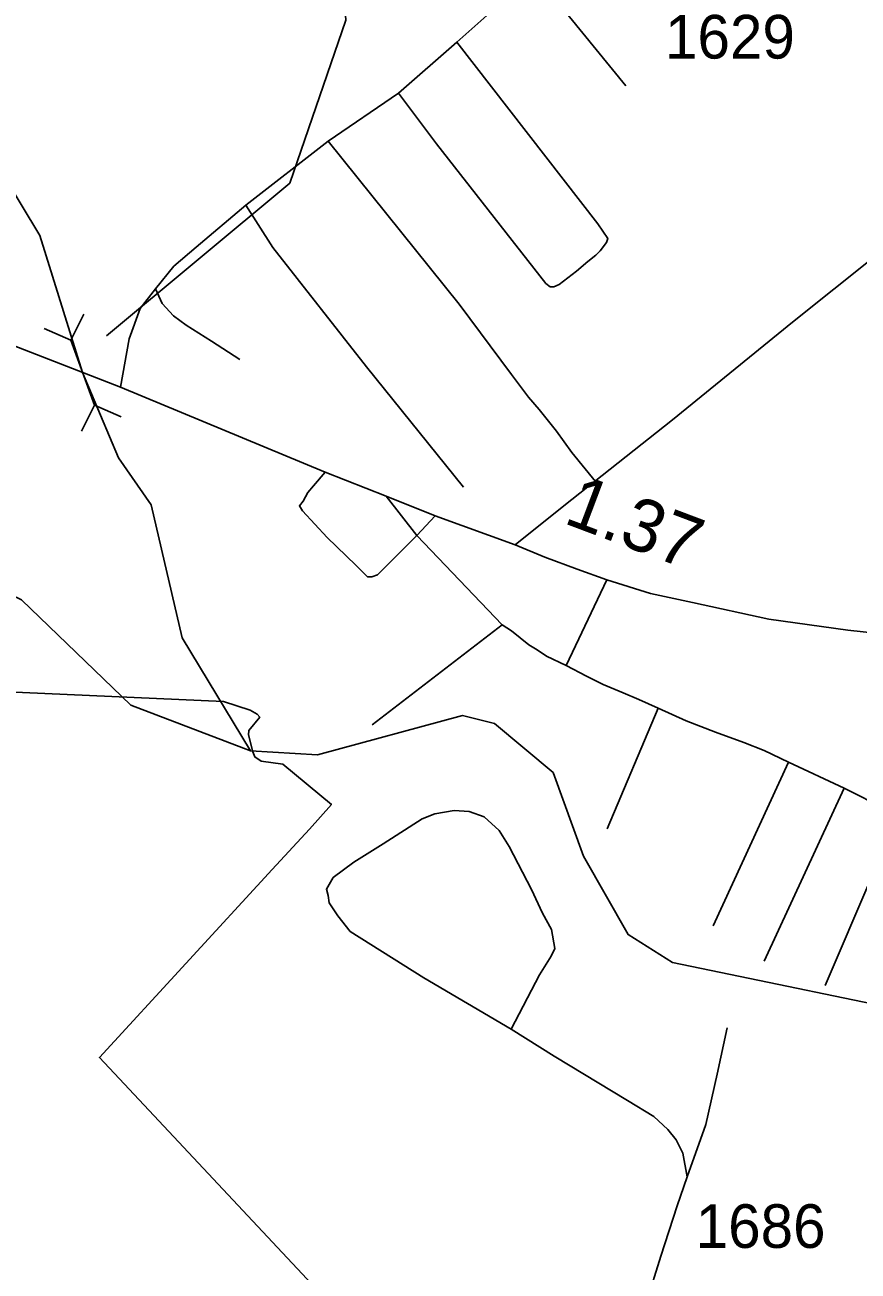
# Model space of a CAD drawing. Extents: x 2290615 to 2522933, y 819489 to 1012715.
# Drawn here: x 2393947 to 2396333, y 979017 to 982586 of the extents above; entities that cross this region are included whole.
import ezdxf

# ---------------------------------------------------------------- set-up
doc = ezdxf.new("R2010")
doc.units = 0
for name, color, linetype in [('Exist Boundary Political City Limit New', 7, 'Continuous'), ('Exist Boundary Political City Limit Old', 7, 'Continuous'), ('Exist Hydrographic Creek Single Shore', 7, 'Continuous'), ('Exist Road Non-System Type 51', 7, 'Continuous'), ('Exist Road Primary US Attributed', 7, 'Continuous'), ('Exist Road Primary US Mileage Hundredths English Label', 7, 'Continuous'), ('Exist Road Primary US Structure Culvert CELL', 7, 'Continuous'), ('Exist Road Primary US Structure Culvert Number Label', 7, 'Continuous'), ('Exist Road Secondary Type 51 Number Label', 7, 'Continuous'), ('Map Preparation Boundary City Limit Buffer Line', 7, 'Continuous')]:
    doc.layers.add(name, color=color, linetype=linetype)

msp = doc.modelspace()

# ---------------------------------------------------------------- linework, layer by layer
at = {"layer": 'Exist Boundary Political City Limit New'}
for points in [[(2393618.8, 980687.8), (2394515, 980647.9), (2394591.5, 980623), (2394611.9, 980611.5), (2394619.1, 980603.4), (2394588.3, 980565), (2394587.3, 980552.5), (2394598.9, 980503.4), (2394605.1, 980489.2), (2394623.3, 980476.9), (2394685.7, 980468.7), (2394824.5, 980353.1), (2394761.3, 980282)], [(2394761.3, 980282), (2394654.9, 980166.6), (2394160.2, 979627.9), (2395391.9, 978313.4)]]:
    msp.add_lwpolyline(points, dxfattribs=at)
at = {"layer": 'Exist Boundary Political City Limit Old'}
for points in [[(2393618.8, 980687.8), (2394515, 980647.9), (2394591.5, 980623), (2394611.9, 980611.5), (2394619.1, 980603.4), (2394588.3, 980565), (2394587.3, 980552.5), (2394598.9, 980503.4), (2394605.1, 980489.2), (2394623.3, 980476.9), (2394685.7, 980468.7), (2394824.5, 980353.1), (2394761.3, 980282)], [(2394761.3, 980282), (2394654.9, 980166.6), (2394160.2, 979627.9), (2395391.9, 978313.4)]]:
    msp.add_lwpolyline(points, dxfattribs=at)
at = {"layer": 'Exist Hydrographic Creek Single Shore'}
for points in [[(2393879.5, 982165.1), (2393989.6, 981982.5), (2394111.7, 981590.2), (2394214.7, 981346.3), (2394308.5, 981211), (2394396.7, 980830.6), (2394592.7, 980507)], [(2394592.7, 980507), (2394249.6, 980637.4), (2393936.5, 980939.6), (2393785.6, 981012.2), (2393361.6, 981007.9), (2393260.7, 981039.9), (2392687.6, 981492.4), (2392479.6, 981480.6), (2392349.6, 981235.5), (2392242.6, 981142.4), (2392002.7, 981024.2), (2391774.7, 980621)], [(2397518.6, 979136.9), (2397397.3, 979259.2), (2397358.2, 979428.8), (2397320.4, 979504.4), (2397230.5, 979527.9), (2397012.7, 979572.4), (2396904.7, 979581.1), (2396594.6, 979735.8), (2395800.7, 979900), (2395674.5, 979980.2), (2395546.6, 980204.8), (2395459.7, 980444.2), (2395291.5, 980585), (2395199.6, 980607.5), (2394784.6, 980495.2), (2394592.7, 980507)]]:
    msp.add_lwpolyline(points, dxfattribs=at)
at = {"layer": 'Exist Road Non-System Type 51'}
for p, q in [((2395183.3, 982536.4), (2395405.1, 982733.7)), ((2395183.3, 982536.4), (2395405.1, 982733.7)), ((2395405.1, 982733.7), (2395667.4, 982411.3)), ((2395405.1, 982733.7), (2395667.4, 982411.3)), ((2395016.1, 982390.2), (2395183.3, 982536.4)), ((2395016.1, 982390.2), (2395183.3, 982536.4)), ((2394815.4, 982252.8), (2395016.1, 982390.2)), ((2394815.4, 982252.8), (2395016.1, 982390.2)), ((2394579.5, 982069.5), (2394815.4, 982252.8)), ((2394579.5, 982069.5), (2394815.4, 982252.8)), ((2395068.9, 981123.4), (2394980.9, 981236.2)), ((2395068.9, 981123.4), (2394980.9, 981236.2)), ((2395068.9, 981123.4), (2395121.7, 981179.8)), ((2395068.9, 981123.4), (2395313.6, 980868)), ((2395068.9, 981123.4), (2395313.6, 980868)), ((2395496.5, 980750.7), (2395612.9, 980996.6)), ((2395496.5, 980750.7), (2395612.9, 980996.6)), ((2394941.1, 980580.9), (2395313.6, 980868)), ((2394941.1, 980580.9), (2395313.6, 980868)), ((2395614.2, 980282.9), (2395760.1, 980628.5)), ((2395614.2, 980282.9), (2395760.1, 980628.5)), ((2395917.9, 980005.7), (2396133.8, 980474.3)), ((2395917.9, 980005.7), (2396133.8, 980474.3)), ((2396133.8, 980474.3), (2396293.1, 980399.8)), ((2396133.8, 980474.3), (2396293.1, 980399.8)), ((2396063.8, 979904.4), (2396293.1, 980399.8)), ((2396063.8, 979904.4), (2396293.1, 980399.8)), ((2396293.1, 980399.8), (2396448, 980320.9)), ((2396293.1, 980399.8), (2396448, 980320.9)), ((2396238.1, 979834.4), (2396372.1, 980146.5)), ((2396238.1, 979834.4), (2396372.1, 980146.5))]:
    msp.add_line(p, q, dxfattribs=at)
for points in [[(2395183.3, 982536.4), (2395587.3, 982015.8), (2395616.4, 981974.4), (2395612, 981962.9), (2395594, 981938.9), (2395581.3, 981926.3), (2395558.8, 981908.1), (2395526.6, 981881), (2395476.4, 981842.3), (2395461.5, 981836.1), (2395450.9, 981836.1), (2395438.6, 981844.9), (2395125.2, 982245.7), (2395016.1, 982390.2)], [(2395183.3, 982536.4), (2395587.3, 982015.8), (2395616.4, 981974.4), (2395612, 981962.9), (2395594, 981938.9), (2395581.3, 981926.3), (2395558.8, 981908.1), (2395526.6, 981881), (2395476.4, 981842.3), (2395461.5, 981836.1), (2395450.9, 981836.1), (2395438.6, 981844.9), (2395125.2, 982245.7), (2395016.1, 982390.2)], [(2395350.6, 981097), (2395489.6, 981208), (2395801.2, 981454.7), (2396144.5, 981734.8), (2396500.1, 982018.4), (2396739.5, 982205.2), (2396852.2, 982291.5)], [(2395580.8, 981278.1), (2395513.3, 981361.6), (2395468.7, 981422.2), (2395419.6, 981484), (2395388.7, 981519.5), (2395340, 981585), (2395190.4, 981785.9), (2394815.4, 982252.8)], [(2395580.8, 981278.1), (2395513.3, 981361.6), (2395468.7, 981422.2), (2395419.6, 981484), (2395388.7, 981519.5), (2395340, 981585), (2395190.4, 981785.9), (2394815.4, 982252.8)], [(2394320.7, 981829.9), (2394373.5, 981895.1), (2394436.9, 981949.7), (2394579.5, 982069.5)], [(2394320.7, 981829.9), (2394373.5, 981895.1), (2394436.9, 981949.7), (2394579.5, 982069.5)], [(2395202.9, 981262.1), (2394924.5, 981606.2), (2394657, 981948), (2394579.5, 982069.5)], [(2394220.4, 981548), (2394245, 981687.2), (2394276.7, 981773.5), (2394320.7, 981829.9)], [(2394220.4, 981548), (2394245, 981687.2), (2394276.7, 981773.5), (2394320.7, 981829.9)], [(2394561.9, 981627.3), (2394480.9, 981680.2), (2394408.7, 981726), (2394371.8, 981752.4), (2394340.1, 981787.6), (2394320.7, 981829.9)], [(2394561.9, 981627.3), (2394480.9, 981680.2), (2394408.7, 981726), (2394371.8, 981752.4), (2394340.1, 981787.6), (2394320.7, 981829.9)], [(2394806.6, 981304.9), (2394773.2, 981266.2), (2394757.3, 981246.8), (2394743.2, 981222.1), (2394732.7, 981208), (2394741.5, 981193.9), (2394811.9, 981118.2), (2394894.6, 981038.9), (2394928.1, 981005.4), (2394940.4, 981005.4), (2394956.2, 981010.7), (2395068.9, 981123.4)], [(2395313.6, 980868), (2395340, 980850.4), (2395389.3, 980809.9), (2395413.9, 980795.8), (2395440.3, 980778.1), (2395496.5, 980750.7)], [(2395496.5, 980750.7), (2395554.6, 980720.9), (2395602.3, 980697.1), (2395660.3, 980673.2), (2395705, 980653.9), (2395760.1, 980628.5)], [(2395496.5, 980750.7), (2395554.6, 980720.9), (2395602.3, 980697.1), (2395660.3, 980673.2), (2395705, 980653.9), (2395760.1, 980628.5)], [(2395760.1, 980628.5), (2395840.5, 980592.8), (2395923.9, 980560), (2396005.8, 980530.2), (2396063.8, 980507.8), (2396133.8, 980474.3)], [(2395760.1, 980628.5), (2395840.5, 980592.8), (2395923.9, 980560), (2396005.8, 980530.2), (2396063.8, 980507.8), (2396133.8, 980474.3)], [(2395338.9, 979709.9), (2395088.7, 979856.9), (2394878.3, 979989), (2394842.8, 980033.9), (2394818.3, 980071.3), (2394815.4, 980092.7), (2394810.2, 980110.9), (2394829.8, 980143.6), (2394888.5, 980188), (2394972.1, 980240.3), (2395084.3, 980312.1), (2395120.9, 980326.5), (2395175.7, 980335.6), (2395218.8, 980333), (2395261.9, 980317.3), (2395304.9, 980278.1), (2395333.6, 980232.4), (2395397.6, 980109.6), (2395428.9, 980041.7), (2395455, 979994.7), (2395463.9, 979940.3), (2395454, 979918.4), (2395420.2, 979864.8), (2395338.9, 979709.9)], [(2395843.1, 979286.7), (2395831.2, 979354.3), (2395811.3, 979392), (2395787.5, 979421.8), (2395747.8, 979459.6), (2395672.4, 979505.3), (2395461.9, 979632.4), (2395338.9, 979709.9)], [(2395843.1, 979286.7), (2395831.2, 979354.3), (2395811.3, 979392), (2395787.5, 979421.8), (2395747.8, 979459.6), (2395672.4, 979505.3), (2395461.9, 979632.4), (2395338.9, 979709.9)], [(2395843.1, 979286.7), (2395897, 979436.5), (2395929.1, 979580.9), (2395957.5, 979713.2)], [(2395843.1, 979286.7), (2395897, 979436.5), (2395929.1, 979580.9), (2395957.5, 979713.2)], [(2395771.6, 978561.8), (2395723.7, 978632.2), (2395695.8, 978684.8), (2395683.4, 978709.6), (2395681.9, 978752.9), (2395700.5, 978833.4), (2395726.7, 978927.8), (2395767.7, 979059.3), (2395814.1, 979203.4), (2395843.1, 979286.7)], [(2395771.6, 978561.8), (2395723.7, 978632.2), (2395695.8, 978684.8), (2395683.4, 978709.6), (2395681.9, 978752.9), (2395700.5, 978833.4), (2395726.7, 978927.8), (2395767.7, 979059.3), (2395814.1, 979203.4), (2395843.1, 979286.7)]]:
    msp.add_lwpolyline(points, dxfattribs=at)
at = {"layer": 'Exist Road Primary US Attributed'}
msp.add_lwpolyline([(2393877.1, 981681.9), (2394220.4, 981548), (2394806.6, 981304.9), (2394980.9, 981236.2), (2395121.7, 981179.8), (2395350.6, 981097), (2395435.1, 981061.8), (2395528.4, 981026.6), (2395612.9, 980996.6), (2395737.9, 980957.8), (2395858.4, 980931.7), (2396077.2, 980884.1), (2396303.6, 980852), (2396488.2, 980832.6), (2396735.4, 980811.8), (2397007.9, 980790.9), (2397228.2, 980767.1), (2397418.8, 980739.5), (2397552.8, 980703.8), (2397677.9, 980674), (2397820.9, 980632.3), (2398023.4, 980566), (2398423.9, 980425.2)], dxfattribs=at)
at = {"layer": 'Exist Road Primary US Structure Culvert CELL'}
for p, q in [((2394115.2, 981757.9), (2394077.9, 981683.4)), ((2394001.5, 981716.6), (2394077.9, 981683.4)), ((2394077.9, 981683.4), (2394145.5, 981496.9)), ((2394108.2, 981422.5), (2394145.5, 981496.9)), ((2394221.9, 981463.7), (2394145.5, 981496.9))]:
    msp.add_line(p, q, dxfattribs=at)
at = {"layer": 'Exist Road Primary US Structure Culvert Number Label'}
msp.add_lwpolyline([(2394180.3, 981695.6), (2394705.2, 982133), (2394865.6, 982599.5), (2394843.7, 982920.3)], dxfattribs=at)
at = {"layer": 'Map Preparation Boundary City Limit Buffer Line'}
for points in [[(2393618.8, 980687.8), (2394515, 980647.9), (2394591.5, 980623), (2394611.9, 980611.5), (2394619.1, 980603.4), (2394588.3, 980565), (2394587.3, 980552.5), (2394598.9, 980503.4), (2394605.1, 980489.2), (2394623.3, 980476.9), (2394685.7, 980468.7), (2394824.5, 980353.1), (2394761.3, 980282)], [(2394761.3, 980282), (2394654.9, 980166.6), (2394160.2, 979627.9), (2395391.9, 978313.4)]]:
    msp.add_lwpolyline(points, dxfattribs=at)

# ---------------------------------------------------------------- texts
at = {"layer": 'Exist Road Primary US Mileage Hundredths English Label'}
msp.add_text('1.37', height=150, rotation=339.3104, dxfattribs=at).set_placement((2395485.5, 981160.4))
at = {"layer": 'Exist Road Secondary Type 51 Number Label'}
for s, p in [('1629', (2395779.7, 982489.6)), ('1686', (2395867.6, 979082.9))]:
    msp.add_text(s, height=125, dxfattribs=at).set_placement(p)

doc.saveas('drawing.dxf')
